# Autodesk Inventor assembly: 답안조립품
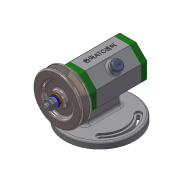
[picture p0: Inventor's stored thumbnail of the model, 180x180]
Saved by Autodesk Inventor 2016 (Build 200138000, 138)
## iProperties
Created: 2017-06
Part Number: 답안조립품
Document SubType Name: Assembly
Designer: KSEW
Author: KSEW
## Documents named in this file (14)
- D:\470607V1007\답안조립품.iam
- D:\470607V1007\본체.ipt
- D:\470607V1007\V벨트풀리.ipt
- D:\470607V1007\고무캡.ipt
- D:\470607V1007\너트 M 8.ipt
- D:\470607V1007\뒤커버.ipt
- D:\470607V1007\베어링 15 x 32 x 9.ipt
- D:\470607V1007\볼트 M4 x 12.ipt
- D:\470607V1007\스프링와셔 8.ipt
- D:\470607V1007\앞커버.ipt
- D:\470607V1007\오일 실 15 25 7.ipt
- D:\470607V1007\와셔 8x17.ipt
- D:\470607V1007\축.ipt
- D:\470607V1007\키 3 x 3 x 12.ipt
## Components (2 placed, 2 different names)
1. V벨트풀리:1 — 각도:8
2. 고무캡:1 — 각도:1
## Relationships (2: Angle 2)
- 각도:1 [Angle]: 고무캡:1
- 각도:8 [Angle]: V벨트풀리:1
